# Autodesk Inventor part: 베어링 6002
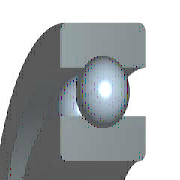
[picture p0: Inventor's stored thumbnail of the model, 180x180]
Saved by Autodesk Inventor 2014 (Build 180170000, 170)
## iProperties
Created: 2012-02
Part Number: 베어링 6002
Material: 강철, 연강
Description: 깊은 그루브 볼 베어링
Document SubType Name: Modeling
Standard: KS B 2023
Designer: mduedu
Standards Organization: KS
Language: ko-KR
Size Designation: 6002 - 15 x 32 x 9
Categories: <MemberInstance><Categories><Category DisplayName="샤프트 부품" InternalName="7f7aeb1f-a693-4053-b835-cee3144e0d98" Mnemonic="SHFT"><Category DisplayName="베어링" Inter
Density: 7.86 g/cm^3
Mass: 27.6801 g
Surface Area: 39.9079 cm^2
Volume: 3.52164 cm^3
Appearance: 분홍색
IsCustomPart: 1
Author: mduedu
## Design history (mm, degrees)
sketch "스케치" dims "d0" = 4.42 (= -0.26 x WD + 0.26 x BD)
  geometry: L1 (2.29, 11.75)-(6.71, 11.75); L2 (4.5, 11.75)-(4.5, 9.54); L3 (4.5, 11.75)-(4.5, 13.96); L4 (2.858, 10.271)-(0, 10.271); L5 (0, 7.5)-(9, 7.5); L6 (2.858, 13.229)-(0, 13.229); L7 (0, 16)-(9, 16); L8 (9, 7.5)-(9, 10.271); L9 (6.142, 10.271)-(9, 10.271); L10 (6.142, 13.229)-(9, 13.229); L11 (9, 16)-(9, 13.229); L12 (-1.4, 0)-(8.4, 0) reference; L13 (0, -0.3)-(0, 5.3) reference
  constraints: 22 end point, 4 point on line, 2 collinear, 2 perpendicular, 2 symmetric about line, 1 midpoint, 1 parallel, 14 other
  dimensions: "d9" = 15 diameter of L5 L12 (= WD); "d11" = 32 diameter of L7 L12 (= BD); "d12" = 9 distance between parallel lines of L8 L13 (= KB); "d13" = 20.542 diameter of L9 L12 (= 0.326 x BD + 0.674 x WD)
revolve "본체" stored, may be unused: angle "d6" = 90 deg
revolve "볼" stored, may be unused: angle "d7" = 90 deg
pattern_circular "IDS_ARRAYBALL[SIMPL:T]" dims angle "d3" = 360 deg
body "Solid1"
fillet "모깎기1" dims "d1" = 0.3 (= KRS)
other parameters: "WD" = 15 [user parameter; used in 5 equation terms], "BD" = 32 [user parameter; used in 5 equation terms], "KB" = 9 [user parameter; used in 1 equation term], "KRS" = 0.3 [user parameter; used in 1 equation term], "d4" = 0, "d5" = 0, "d8" = 0, "d14" = 0, "d15" = 0, "BBA" = 0 [user parameter], "BC0" = 2850000 [user parameter], "BC" = 5590000 [user parameter], "BR" = 16 (= 0.5 x BD) [user parameter], "WR" = 7.5 (= 0.5 x WD) [user parameter]
